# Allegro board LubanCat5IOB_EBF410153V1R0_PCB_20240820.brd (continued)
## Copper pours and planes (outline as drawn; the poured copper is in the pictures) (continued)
VCC_3V3_S3 on ART03: 36.17,18.35 32.74,18.35 32.11,17.72 32.11,14.39 31.62,13.91 25.83,13.91 25.35,14.39 25.35,18.81 24.84,19.32 4.11,19.32 3.71,18.91 3.71,17.24 4.04,16.91 22.73,16.91 23.09,16.55 23.09,12.84 23.75,12.18 33.68,12.18 34.06,12.56 34.06,16.65 34.57,17.16 36.14,17.16 36.4,17.41 36.4,18.13
VCC_3V3_S3 on ART04: 9.63,65.85 9.17,66.31 9.17,86.96 8.97,87.16 6.91,87.16 6.71,86.96 6.71,63.51 7.49,62.73 22.78,62.73 23.37,62.14 23.37,58.18 23.83,57.72 28.09,57.72 28.75,57.06 28.75,54.24 29.08,53.91 31.11,53.91 31.45,53.58 31.45,36.31 31.95,35.8 34.32,35.8 34.85,35.27 34.85,17.82 34.98,17.69 36.35,17.69 36.5,17.85 36.5,36.72 36.09,37.12 33.32,37.12 32.69,37.76 32.69,55.72 31.45,56.96 31.45,59.93 30.73,60.64 26.72,60.64 26.01,61.36 26.01,65.45 25.6,65.85
VCC_3V3_S3 on ART04: 95.94,38.6 96.01,38.42 96.19,38.34 97.36,38.34 97.54,38.42 97.61,38.6 97.61,38.78 97.54,38.95 97.36,39.03 96.19,39.03 96.01,38.95 95.94,38.78
VCC_3V3_S3 on PWR05: 34.77,17.36 34.85,17.18 35.03,17.11 39.75,17.11 39.93,17.18 40.01,17.36 40.01,18.07 39.93,18.25 39.75,18.33 35.03,18.33 34.85,18.25 34.77,18.07
VCC_5V0_S0 on TOP: 161.85,50.82 161.85,48.43 162.05,48.22 163.37,48.22 163.37,50.82 163.18,51.02 162.04,51.02
VCC_5V0_S0 on TOP: 40.51,71.41 40.59,71.23 40.77,71.16 41.78,71.16 41.96,71.23 42.04,71.41 42.04,72.58 41.96,72.76 41.78,72.84 40.77,72.84 40.59,72.76 40.51,72.58
VCC_5V0_S0 on TOP: 28.7,70.3 28.78,70.12 28.96,70.04 30.05,70.04 30.23,70.12 30.3,70.3 30.3,71.49 30.23,71.67 30.05,71.74 28.96,71.74 28.78,71.67 28.7,71.49
VCC_5V0_S0 on TOP: 162.03,83.25 162.1,83.07 162.28,83 163.12,83 163.3,83.07 163.37,83.25 163.37,84.24 163.3,84.42 163.12,84.5 162.28,84.5 162.1,84.42 162.03,84.24
VCC_5V0_S0 on TOP: 161.85,68.3 161.85,65.81 162.05,65.61 163.37,65.61 163.37,66.9 163.47,67 163.75,67 163.86,67.11 163.86,68.3 163.73,68.43 161.98,68.43
VCC_5V0_S0 on TOP: 127.64,34.43 127.64,32.6 127.43,32.4 125.88,32.4 125.68,32.6 125.68,33.85 126.8,33.85 127.03,34.08 127.03,34.43
VCC_5V0_S0 on TOP: 12.57,65.98 22.05,65.98 22.68,65.34 24.66,65.34 24.97,65.04 24.97,64.38 26.16,64.38 26.16,66.31 25.86,66.61 23.16,66.61 21.89,67.88 20.5,67.88 20.12,68.26 16.28,68.26 16.03,68.01 16.03,67.63 15.77,67.38 12.57,67.38
VCC_5V0_S0 on BOTTOM: 163.19,32.1 149.1,32.1 148.95,32.25 148.95,34.41 149.12,34.58 162.1,34.58 162.31,34.38 162.31,33.54 162.48,33.37 163.37,33.37 163.37,32.27
VCC_5V0_S0 on BOTTOM: 161.85,48.86 161.92,48.68 162.1,48.61 163.19,48.61 163.37,48.68 163.45,48.86 163.45,50.79 163.37,50.97 163.19,51.04 162.1,51.04 161.92,50.97 161.85,50.79
VCC_5V0_S0 on BOTTOM: 161.95,68.43 163.27,68.43 163.37,68.32 163.37,67.56 163.53,67.41 163.73,67.41 163.86,67.28 163.86,67.08 163.78,67 161.93,67 161.82,67.11 161.82,68.3
VCC_5V0_S0 on BOTTOM: 125.58,32.58 125.65,32.4 125.83,32.32 127.2,32.32 127.38,32.4 127.46,32.58 127.46,33.62 127.38,33.8 127.2,33.87 125.83,33.87 125.65,33.8 125.58,33.62
VCC_5V0_S0 on BOTTOM: 11.68,84.39 11.76,84.21 11.94,84.14 12.85,84.14 13.03,84.21 13.11,84.39 13.11,86.17 13.03,86.35 12.85,86.43 11.94,86.43 11.76,86.35 11.68,86.17
VCC_5V0_S0 on ART03: 20.7,65.8 24.87,65.8 25.35,66.28 25.35,69.66 25.88,70.2 32.84,70.2 33.1,70.45 33.1,71.26 33.35,71.52 41.83,71.52 42.11,71.8 42.11,72.76 41.91,72.96 22.96,72.96 22.66,72.66 22.66,69.56 22.4,69.31 20.65,69.31 20.45,69.1 20.45,66.05
VCC_5V0_S0 on ART04: 120.45,28.69 120.19,28.95 120.19,30.29 120.5,30.6 125.2,30.6 125.5,30.9 125.5,32.63 125.68,32.81 127.58,32.81 127.79,32.6 127.79,30.88 128.07,30.6 131.72,30.6 133.96,32.83 147.9,32.83 148.16,33.09 148.16,34.41 148.31,34.56 149.3,34.56 149.5,34.36 149.5,30.85 148.95,30.29 135.05,30.29 133.45,28.69
VCC_5V0_S0 on ART04: 161.85,17.17 161.85,59.56 162.15,59.87 162.97,59.87 163.27,60.17 163.27,66.8 163.07,67 162.05,67 161.85,67.21 161.85,96.43 161.06,97.22 99.9,97.22 99.42,97.7 99.42,98.22 95,98.22 95,97.31 94.69,97 88.98,97 88.67,97.31 88.67,98.98 44.86,98.98 43.71,97.84 39.32,97.84 38.94,97.46 38.94,94.07 38.29,93.42 14.63,93.42 14.02,92.81 14.02,85.05 14.35,84.72 15.34,84.72 15.82,84.24 15.82,70.2 16.26,69.76 20.14,69.76 20.52,69.38 20.52,68.06 20.78,67.81 21.72,67.81 22.02,67.5 22.02,66.21 21.79,65.98 9.98,65.98 9.5,66.46 9.5,96.03 9.88,96.41 16.03,96.41 16.72,97.1 27.64,97.1 28.02,97.48 28.02,101.46 28.53,101.98 165.89,101.98 166.55,101.32 166.55,17.08 166,16.53 162.48,16.53
VCC_12V on TOP: 11.96,51.74 11.96,54.05 12.24,54.33 16.64,54.33 16.92,54.05 16.92,52.32 15.49,52.32 14.91,51.74
VCC_12V on TOP: 44.91,71.36 44.98,71.18 45.16,71.11 46.18,71.11 46.36,71.18 46.43,71.36 46.43,72.56 46.36,72.74 46.18,72.81 45.16,72.81 44.98,72.74 44.91,72.56
VCC_12V on TOP: 155.96,48.71 156.03,48.53 156.21,48.45 157.56,48.45 157.74,48.53 157.81,48.71 157.81,53.05 157.74,53.23 157.56,53.3 156.21,53.3 156.03,53.23 155.96,53.05
VCC_12V on TOP: 17.58,29.08 15.14,29.08 14.99,28.93 11.33,28.93 11.15,29.11 11.15,31.39 11.35,31.6 15.01,31.6 15.01,30.38 15.21,30.17 16.03,30.17 16.23,29.97 16.23,29.51 16.38,29.36 17.58,29.36 17.63,29.31 17.63,29.13
VCC_12V on TOP: 9.98,18.36 10.06,18.18 10.24,18.11 13.41,18.11 13.59,18.18 13.67,18.36 13.67,20.27 13.59,20.45 13.41,20.52 10.24,20.52 10.06,20.45 9.98,20.27
VCC_12V on TOP: 13.28,74.72 13.28,77.64 13.11,77.82 12.78,77.82 12.6,77.99 12.6,79.62 12.42,79.8 11.94,79.8 11.71,80.02 11.71,81.85 11.56,82.01 11.28,82.01 11.1,82.18 11.1,82.67 10.97,82.79 10.03,82.79 10.03,84.6 13.61,84.6 13.87,84.85 16.15,84.85 16.15,82.31 15.98,82.13 15.57,82.13 15.44,82.01 15.44,74.72 15.27,74.54 13.46,74.54
VCC_12V on TOP: 33.5,69.84 33.58,69.66 33.76,69.59 34.75,69.59 34.93,69.66 35,69.84 35,70.91 34.93,71.09 34.75,71.16 33.76,71.16 33.58,71.09 33.5,70.91
VCC_12V on TOP: 152.12,68.58 152.12,66.69 151.94,66.51 149.76,66.51 149.61,66.66 149.61,67.78 149.76,67.93 150.72,67.93 150.88,68.09 150.88,68.76 151.94,68.76
VCC_12V on TOP: 12.37,48.49 12.37,46.02 16.71,46.02 16.92,46.23 16.92,47.14 15.09,47.14 14.81,47.42 14.81,48.46 14.63,48.64 12.52,48.64
VCC_12V on TOP: 11.96,57.73 11.96,59.36 12.22,59.61 16.69,59.61 16.94,59.36 16.94,58.01 15.19,58.01 14.91,57.73
VCC_12V on TOP: 12.24,37.69 16.71,37.69 16.92,37.49 16.92,36.22 16.71,36.02 12.29,36.02 12.09,36.22 12.09,37.54
VCC_12V on TOP: 151,53.28 152.4,53.28 152.58,53.1 152.58,49.72 152.37,49.52 150.06,49.52 149.91,49.67 149.91,51.75 150.06,51.91 150.85,51.91 151,52.06
VCC_12V on TOP: 19.56,38.61 19.63,38.43 19.81,38.35 22.35,38.35 22.53,38.43 22.61,38.61 22.61,40.13 22.53,40.31 22.35,40.38 19.81,40.38 19.63,40.31 19.56,40.13
VCC_12V on BOTTOM: 149.91,49.72 149.99,49.54 150.16,49.47 151.99,49.47 152.17,49.54 152.25,49.72 152.25,51.65 152.17,51.83 151.99,51.91 150.16,51.91 149.99,51.83 149.91,51.65
VCC_12V on BOTTOM: 155.93,48.73 156,48.55 156.18,48.48 157.35,48.48 157.53,48.55 157.61,48.73 157.61,51.65 157.53,51.83 157.35,51.91 156.18,51.91 156,51.83 155.93,51.65
VCC_12V on ART03: 33.38,69.66 33.38,71.11 33.58,71.31 41.99,71.31 42.39,71.72 42.39,72.94 42.09,73.24 29.95,73.24 29.64,73.55 29.64,75.55 29.24,75.96 23.34,75.96 23.09,76.21 23.09,79.19 23.27,79.36 30.81,79.36 33.88,76.29 34.98,76.29 35.61,75.66 45.59,75.66 46.41,74.84 46.41,69.74 46.13,69.46 33.58,69.46
VCC_12V on ART04: 41.86,9.78 41.86,11.32 43.59,11.32 43.94,11.67 43.94,12.39 44.3,12.75 99.8,12.75 100.84,13.79 100.84,19.93 101.35,20.44 104.06,20.44 104.6,19.9 104.6,14.87 105.23,14.24 153.06,14.24 157.58,18.76 157.58,47.67 157.28,47.98 155.22,47.98 154.91,48.28 154.91,48.89 154.58,49.22 149.66,49.22 149.3,49.58 149.3,61.57 149.66,61.92 160.63,61.92 160.88,62.18 160.88,64.79 160.71,64.97 151.33,64.97 151.08,65.23 151.08,65.78 150.9,65.96 150.14,65.96 150.11,65.94 149.76,65.94 149.53,66.17 149.53,67.79 149.78,68.05 161.95,68.05 163.27,66.72 163.27,60.35 162.84,59.92 162.23,59.92 161.62,59.31 161.62,15.46 160.73,14.57 158.6,14.57 157.07,13.05 157.07,10.86 155.99,9.78
VCC_12V on PWR05: 9.78,80.25 9.78,12.28 10.44,11.62 41,11.62 41.35,11.27 41.35,10.03 41.58,9.8 43.26,9.8 43.48,10.03 43.48,15.52 42.98,16.03 20.83,16.03 19.81,17.04 19.81,36.83 20.6,37.62 22.45,37.62 22.96,38.12 22.96,41.58 22.53,42.01 20.22,42.01 19.81,42.42 19.81,76.06 20.24,76.49 23.29,76.49 23.7,76.9 23.7,80.43 23.44,80.69 10.21,80.69
VCCA1V8_CODEC on BOTTOM: 17.35,69.81 17.35,70.63 16.69,71.29 16.69,76.55 16.79,76.65 18.72,76.65 18.72,73.7 18.34,73.32 18.34,69.92 18.24,69.81
VCCA3V3_CODEC on BOTTOM: 22.12,69.86 22.12,70.7 21.92,70.91 21.92,74.36 23.55,74.36 23.55,73.75 22.63,73.75 22.53,73.65 22.53,71.19 22.91,70.8 22.91,69.86
VCCA_1V8_S0 on TOP: 38.58,16.07 39.75,16.07 39.95,15.86 44.86,15.86 45.54,16.55 45.54,18.02 45.77,18.02 45.77,15.69 45.24,15.15 40.18,15.15 40.01,15.33 38.58,15.33 38.48,15.43 38.48,15.97
VCCA_1V8_S0 on BOTTOM: 18.95,70.65 18.95,68.39 19.18,68.16 21.84,68.16 22.02,68.34 22.02,68.77 21.82,68.98 19.91,68.98 19.76,69.13 19.76,70.65
VCCA_1V8_S0 on ART04: 20.95,68.7 23.16,68.7 23.39,68.47 23.39,67.68 23.75,67.32 27.41,67.32 27.81,66.92 27.81,63.41 28.42,62.8 30.78,62.8 33.15,60.44 33.15,57.67 34.62,56.2 34.62,38.95 34.87,38.7 37.87,38.7 38.23,38.34 38.23,16.58 38.46,16.35 39.9,16.35 40.13,16.12 40.13,15.2 39.9,14.98 36.83,14.98 36.65,15.15 36.65,36.77 36.14,37.28 33.45,37.28 32.87,37.86 32.87,55.87 31.62,57.11 31.62,60.04 30.78,60.87 26.92,60.87 26.21,61.58 26.21,65.62 25.86,65.98 22.43,65.98 22.23,66.18 22.23,67.63 21.82,68.04 20.95,68.04 20.8,68.19 20.8,68.54
VCCA_3V3_S0 on TOP: 45.09,18.02 45.09,17.16 44.58,16.65 40.36,16.65 39.75,17.26 38.61,17.26 38.48,17.13 38.48,16.73 38.66,16.55 39.6,16.55 40.11,16.04 44.7,16.04 45.42,16.75 45.42,18.02
VCCA_3V3_S0 on BOTTOM: 20.52,70.65 20.52,69.33 20.7,69.15 21.89,69.15 22.02,69.28 22.02,69.56 21.87,69.71 21.44,69.71 21.31,69.84 21.31,70.65
VCCA_3V3_S0 on ART04: 20.95,69.76 26.97,69.76 27.14,69.6 27.14,69.12 27.33,68.93 29.92,68.93 30.18,68.67 30.18,65.65 31.32,64.51 35.31,64.51 36.02,63.79 36.02,40.81 36.3,40.53 39.9,40.53 40.49,39.94 40.49,16.88 40.26,16.65 38.63,16.65 38.4,16.88 38.4,38.5 38.05,38.85 35.05,38.85 34.8,39.11 34.8,56.53 33.5,57.83 33.5,60.59 30.99,63.11 28.65,63.11 28.02,63.74 28.02,67.12 27.58,67.55 23.88,67.55 23.62,67.81 23.62,68.67 23.37,68.93 20.95,68.93 20.8,69.08 20.8,69.61
VDD_CAM0_5V on TOP: 166.6,80.2 165.28,80.2 165.28,80.89 165.18,80.99 163.78,80.99 163.78,81.85 163.63,82.01 162.76,82.01 162.76,82.62 166.42,82.62 166.6,82.44
VDD_CAM1_5V on BOTTOM: 166.62,71.01 165.28,71.01 165.28,70.58 165,70.3 163.78,70.3 163.78,69.41 163.65,69.28 162.76,69.28 162.76,68.65 166.42,68.65 166.62,68.85
VDD_CAM2_5V on TOP: 166.6,62.8 165.3,62.8 165.3,63.34 165.05,63.59 163.78,63.59 163.78,64.4 163.55,64.63 162.76,64.63 162.76,65.24 166.37,65.24 166.6,65.01
VDD_CAM3_5V on BOTTOM: 166.6,53.61 163.93,53.61 163.78,53.46 163.78,52.03 163.6,51.86 162.79,51.86 162.79,51.27 166.37,51.27 166.6,51.5
VDD_CAM4_5V on TOP: 166.6,45.4 165.3,45.4 165.3,46.07 165.18,46.19 163.78,46.19 163.78,47.08 163.63,47.23 162.76,47.23 162.76,47.82 166.32,47.82 166.6,47.54
VDD_CAM5_5V on BOTTOM: 166.6,36.21 165.3,36.21 165.3,35.6 165.07,35.37 163.78,35.37 163.78,34.51 163.6,34.33 162.76,34.33 162.76,33.75 166.37,33.75 166.6,33.97
VDD_LCD0_3V3 on TOP: 7.87,90.13 8.74,90.13 8.94,89.93 8.94,87.39 9.55,86.78 9.55,81.22 9.27,80.94 7.9,80.94 7.9,85.71 7.67,85.94 7.67,89.93
VDD_LCD0_3V3 on BOTTOM: 7.72,90.01 7.72,86.91 7.9,86.73 9.19,86.73 9.19,90.06 9.04,90.21 7.92,90.21
VDD_LCD0_5V on TOP: 7.67,81.93 7.67,85.49 7.42,85.74 7.42,90.01 7.29,90.13 5.77,90.13 5.61,89.98 5.61,82.31 5.99,81.93
VDD_LCD0_5V on BOTTOM: 11.42,90.2 11.18,90.44 7.85,90.44 7.54,90.13 7.54,87.92 7.34,87.72 6.58,87.72 6.38,87.92 6.38,90.9 7.06,91.58 12.04,91.58 12.34,91.28 12.34,86.73 11.58,86.73 11.42,86.9
VDD_LCD1_3V3 on TOP: 15.04,64.38 15.04,65.32 14.63,65.72 9.73,65.72 9.53,65.52 9.53,64.43 9.73,64.23 11.66,64.23 11.81,64.38
VDD_LCD1_3V3 on BOTTOM: 9.45,64.45 9.52,64.28 9.7,64.2 10.87,64.2 11.05,64.28 11.13,64.45 11.13,65.5 11.05,65.68 10.87,65.75 9.7,65.75 9.52,65.68 9.45,65.5
VDD_LCD1_3V3 on BOTTOM: 7.67,70.74 5.77,70.74 5.64,70.61 5.64,70.08 5.79,69.93 7.67,69.93
VDD_LCD1_5V on TOP: 23.67,64.38 20.27,64.38 20.04,64.15 18.72,64.15 18.57,64.3 18.57,65.55 18.72,65.7 21.84,65.7 22.58,64.96 23.67,64.96
VDD_LCD1_5V on BOTTOM: 6.3,69.69 6.3,66.92 6.88,66.33 11.1,66.33 11.46,65.98 11.46,62.75 11.81,62.4 19.84,62.4 20.02,62.58 20.02,66.66 19.58,67.1 13.79,67.1 13.39,67.5 8.05,67.5 7.67,67.88 7.67,69.69
(no net) on TOP: 72.21,75.53 72.36,75.53 72.47,75.43 72.47,75.12 72.57,75.02 72.9,75.02 73,74.92 73,74.18 73.74,73.45 73.74,71.39 72.62,71.39 72.62,73.19 72.14,73.67 72.14,75.45
(no net) on TOP: 55.03,74.3 55.34,73.99 55.34,71.39 54.22,71.39 54.22,73.41 54.06,73.57 54.06,74.76 53.74,75.08 53.74,75.72 53.85,75.83 54.66,75.83 54.8,75.69 54.8,75.34 55.03,75.11
CAN1_H on TOP (solid shape): 95.8,13.05 94.87,12.29 94.18,12.99 94.15,13.05 94.18,13.11 94.87,13.81
CAN2_H on TOP (solid shape): 104.67,13.05 103.75,12.3 103.07,12.99 103.04,13.05 103.07,13.11 103.75,13.8
HDMI0_5V on BOTTOM: 86.23,98.17 86.31,97.99 86.49,97.92 88.52,97.92 88.7,97.99 88.77,98.17 88.77,101.34 88.7,101.52 88.52,101.6 86.49,101.6 86.31,101.52 86.23,101.34
HDMI0_5V on ART04: 84.48,84.43 84.55,84.25 84.73,84.17 88.21,84.17 88.39,84.25 88.47,84.43 88.47,99.36 88.39,99.54 88.21,99.62 84.73,99.62 84.55,99.54 84.48,99.36
HDMI1_5V on BOTTOM: 95.12,98.17 95.2,97.99 95.38,97.92 97.28,97.92 97.46,97.99 97.54,98.17 97.54,101.34 97.46,101.52 97.28,101.6 95.38,101.6 95.2,101.52 95.12,101.34
HDMI1_5V on ART04: 95.2,84.38 95.27,84.2 95.45,84.12 98.96,84.12 99.14,84.2 99.21,84.38 99.21,99.31 99.14,99.49 98.96,99.57 95.45,99.57 95.27,99.49 95.2,99.31
M2EKEY_3V3 on TOP: 159.08,59.1 159.08,62.91 158.75,63.24 158.39,63.24 158.39,64.51 158.55,64.66 160.66,64.66 160.78,64.53 160.78,63.39 160.48,63.08 160.48,59.1
M2EKEY_3V3 on BOTTOM: 158.17,63.49 158.24,63.31 158.42,63.24 160.53,63.24 160.71,63.31 160.78,63.49 160.78,64.43 160.71,64.61 160.53,64.68 158.42,64.68 158.24,64.61 158.17,64.43
M2EKEY_3V3 on BOTTOM: 141.17,63.47 141.25,63.29 141.43,63.22 141.76,63.22 141.94,63.29 142.01,63.47 142.01,66.37 141.94,66.55 141.76,66.62 141.43,66.62 141.25,66.55 141.17,66.37
M2EKEY_3V3 on BOTTOM: 124.49,64.77 124.49,63.12 124.92,62.69 124.92,62.31 124.79,62.18 123.62,62.18 123.49,62.31 123.49,63.02 123.7,63.22 123.7,64.77
M2EKEY_3V3 on ART04: 125.32,62.5 125.32,74.93 125.6,75.21 132.16,75.21 132.54,74.83 132.54,62.76 133.22,62.08 160.32,62.08 160.76,62.51 160.76,64.57 160.53,64.79 142.19,64.79 141.76,65.23 141.76,66.39 141.3,66.85 137.02,66.85 136.42,67.45 136.42,76.77 135.88,77.32 123.02,77.32 122.4,76.7 122.4,62.47 122.75,62.13 124.95,62.13
M2PCIE_3V3 on TOP: 153.7,78.25 152.63,78.25 152.32,78.55 152.32,85.1 152.68,85.46 152.68,87.24 151.03,87.24 150.83,87.04 150.83,77.26 151.28,76.8 153.7,76.8
M2PCIE_3V3 on TOP: 158.17,80.23 156.79,80.23 156.62,80.41 156.62,82.74 156.34,83.02 154.69,83.02 154.43,83.28 154.43,87.24 156.18,87.24 156.18,84.68 156.44,84.43 157.18,84.43 157.4,84.2 157.4,81.83 157.61,81.63 158.19,81.63 158.34,81.47 158.34,80.41
M2PCIE_3V3 on BOTTOM: 168.22,85.29 168.3,85.11 168.48,85.04 170.05,85.04 170.23,85.11 170.31,85.29 170.31,88.21 170.23,88.39 170.05,88.47 168.48,88.47 168.3,88.39 168.22,88.21
M2PCIE_3V3 on ART03: 150.93,80.29 166.85,80.29 167.79,81.23 169.9,81.23 170.18,81.51 170.18,87.4 169.72,87.86 167.59,87.86 167.08,87.35 167.08,83.44 166.78,83.13 152.02,83.13 151.54,83.62 150.95,83.62 150.8,83.46 150.8,80.42
MINIPCIE_3V3 on TOP: 130.28,60.21 130.35,60.03 130.53,59.96 132.26,59.96 132.44,60.03 132.51,60.21 132.51,60.52 132.44,60.7 132.26,60.77 130.53,60.77 130.35,60.7 130.28,60.52
MINIPCIE_3V3 on TOP: 124.99,71.4 125.07,71.22 125.25,71.14 126.16,71.14 126.34,71.22 126.42,71.4 126.42,74.52 126.34,74.7 126.16,74.78 125.25,74.78 125.07,74.7 124.99,74.52
MINIPCIE_3V3 on TOP: 120.45,60.21 120.52,60.03 120.7,59.96 123.8,59.96 123.98,60.03 124.05,60.21 124.05,60.54 123.98,60.72 123.8,60.8 120.7,60.8 120.52,60.72 120.45,60.54
MINIPCIE_3V3 on TOP: 143.81,60.01 144.96,60.01 145.19,60.24 145.19,61.36 144.96,61.58 144.02,61.58 143.81,61.38
MINIPCIE_3V3 on TOP: 153.82,61.43 153.82,62.85 152.27,62.85 152.15,62.98 152.15,66.24 149.83,66.24 149.63,66.04 149.63,63.41 149.81,63.24 150.09,63.24 150.39,62.93 150.39,61.74 150.7,61.43
MINIPCIE_3V3 on BOTTOM: 125.53,73.66 125.6,73.48 125.78,73.4 126.39,73.4 126.57,73.48 126.64,73.66 126.64,74.52 126.57,74.7 126.39,74.78 125.78,74.78 125.6,74.7 125.53,74.52
MINIPCIE_3V3 on BOTTOM: 149.96,65.93 152.07,65.93 152.32,65.67 152.32,62.96 151.74,62.96 151.74,63.34 151.56,63.51 150.01,63.51 149.83,63.69 149.83,65.8
MINIPCIE_3V3 on ART03: 151.08,65.75 150.9,65.93 149.02,65.93 148.82,65.72 148.82,62.45 148.46,62.09 122.78,62.09 122.53,61.84 122.53,60.26 122.76,60.04 150.65,60.04 151.08,60.47
MINIPCIE_3V3 on ART04: 122.78,61.84 125.2,61.84 125.6,62.24 125.6,74.59 125.81,74.79 128.57,74.79 128.96,74.41 128.96,59.78 128.65,59.48 122.73,59.48 122.4,59.81 122.4,61.46
RS232_R2IN on BOTTOM (solid shape): 145.21,14.64 145.26,14.66 145.31,14.64 146,13.95 145.26,13.03 144.51,13.95
RS485_1_B on TOP (solid shape): 121.17,13.05 120.24,12.32 119.58,12.99 119.55,13.05 119.58,13.11 120.24,13.78
SATA_5V0 on TOP: 22.61,33.2 28.63,33.2 28.85,33.43 28.85,34.95 28.65,35.15 26.09,35.15 25.91,34.97 25.91,34.75 25.73,34.57 22.61,34.57
SATA_5V0 on BOTTOM: 26.42,33.78 26.49,33.6 26.67,33.53 28.7,33.53 28.88,33.6 28.96,33.78 28.96,35.18 28.88,35.36 28.7,35.43 26.67,35.43 26.49,35.36 26.42,35.18
SATA_5V0 on ART03: 25.91,34.94 25.91,14.75 26.42,14.24 31.57,14.24 31.83,14.49 31.83,17.16 31.57,17.41 29.34,17.41 28.83,17.92 28.83,34.94 28.57,35.19 26.16,35.19
SATA_12V on TOP: 17.35,23.85 17.35,19.96 17.45,19.86 17.45,18.07 16.84,17.46 16.84,13.1 16.15,12.41 16.15,11.11 16.94,10.33 16.94,8.57 16.67,8.3 11.78,8.3 11.48,8.6 11.48,10.64 12.09,11.25 12.09,13.44 12.52,13.87 14.05,13.87 14.43,14.25 14.43,20.09 14.27,20.24 13.13,20.24 13.13,21.18 14.38,21.18 14.63,21.44 14.63,23.65 14.83,23.85
SATA_12V on BOTTOM: 11.18,8.36 11.25,8.18 11.43,8.1 29.84,8.1 30.02,8.18 30.1,8.36 30.1,11.25 30.02,11.43 29.84,11.51 11.43,11.51 11.25,11.43 11.18,11.25
N16593687 on TOP: 19.76,32.46 19.76,30.68 20.37,30.68 20.37,32.46
N16593695 on TOP: 17.5,28.88 20.13,28.88 20.75,29.5 20.75,32.46 23.27,32.46 23.62,32.1 23.62,31.23 23.9,30.95 25.45,30.95 25.45,29.05 22.43,29.05 21.35,27.96 18.14,27.96 17.96,28.14 17.96,28.45 17.83,28.57 17.5,28.57 17.42,28.65 17.42,28.8
N16594691 on TOP: 18.06,29.11 19.8,29.11 20.37,29.68 20.37,30.3 19.76,30.3 19.76,29.94 19.36,29.54 18.06,29.54 17.98,29.46 17.98,29.18
N16606404 on TOP (solid shape): 72.47,75.43 72.47,75.12 72.57,75.02 72.9,75.02 73,74.92 73,74.18 73.74,73.45 73.74,71.39 72.62,71.39 72.62,73.19 72.14,73.67 72.14,75.45 72.21,75.53 72.36,75.53
N16612146 on TOP (solid shape): 54.21,75.81 54.27,75.8 54.69,75.8 54.8,75.69 54.8,75.34 55.03,75.11 55.03,74.3 55.34,73.99 55.34,71.39 54.22,71.39 54.22,73.41 54.06,73.57 54.06,74.76 53.74,75.08 53.74,75.72 53.85,75.83 54.15,75.83
N16630071 on BOTTOM: 22.94,72.76 24.56,72.76 24.56,74.36 23.95,74.36 23.95,73.5 23.8,73.34 22.94,73.34
N16783872 on TOP: 124.46,76.81 124.53,76.63 124.71,76.55 126.59,76.55 126.77,76.63 126.85,76.81 126.85,78.1 126.77,78.28 126.59,78.36 124.71,78.36 124.53,78.28 124.46,78.1
N16803397 on TOP: 153.24,72.2 153.24,70.02 153.29,69.97 154.18,69.97 154.18,72.07 154.05,72.2
N16803401 on TOP: 150.9,69 152.76,69 153.06,69.31 153.06,72.96 153.29,73.19 153.67,73.19 153.67,74.61 151.38,74.61 151.38,73.22 152.04,73.22 152.22,73.04 152.22,69.84 152.1,69.71 150.9,69.71
N16835425 on TOP: 17.17,47.12 17.17,45.26 17.4,45.03 21.08,45.03 21.34,45.29 21.34,46.33 21.46,46.46 24.77,46.46 24.77,47.83 19.96,47.83 19.71,47.57 19.71,46.23 19.51,46.02 17.98,46.02 17.88,46.13 17.88,47.12
N16835491 on TOP: 18.08,44.04 18.16,43.86 18.34,43.79 20.27,43.79 20.45,43.86 20.52,44.04 20.52,44.5 20.45,44.68 20.27,44.75 18.34,44.75 18.16,44.68 18.08,44.5
N16843509 on TOP: 151,53.53 152.98,53.53 153.16,53.71 153.16,57.53 153.29,57.66 153.8,57.66 153.8,59.05 151.51,59.05 151.51,57.66 151.89,57.66 152.12,57.43 152.12,54.35 151.99,54.22 151,54.22
N16843993 on TOP: 153.37,56.71 153.37,55.23 153.42,55.18 153.42,54.47 154.31,54.47 154.31,56.53 154.13,56.71
N16890968 on TOP: 11.43,73.34 11.43,71.52 11.61,71.34 12.24,71.34 12.24,72.53 12.34,72.63 12.34,73.34
N16890980 on TOP: 14.73,74.28 12.9,74.28 12.65,74.03 12.65,69.76 12.83,69.59 14.86,69.59 14.86,70.98 13.72,70.98 13.59,71.11 13.59,73.5 13.67,73.57 14.73,73.57
N16891638 on TOP: 18.08,55.85 18.16,55.67 18.34,55.6 20.22,55.6 20.4,55.67 20.47,55.85 20.47,56.34 20.4,56.52 20.22,56.59 18.34,56.59 18.16,56.52 18.08,56.34
N16891644 on TOP: 17.17,58.95 17.17,57.07 17.4,56.84 21.26,56.84 21.51,57.1 21.51,58.24 21.79,58.52 24.79,58.52 24.79,59.92 20.09,59.92 19.76,59.59 19.76,57.89 19.61,57.73 18.06,57.73 17.88,57.91 17.88,58.95
N16892291 on TOP: 17.17,53.21 17.17,51.41 17.45,51.13 20.8,51.13 21.01,50.93 21.01,50.29 22.4,50.29 22.4,52.58 20.62,52.58 20.12,52.07 18.06,52.07 17.88,52.25 17.88,53.19 17.86,53.21
N16892339 on TOP: 18.08,50.14 18.16,49.96 18.34,49.88 20.19,49.88 20.37,49.96 20.45,50.14 20.45,50.6 20.37,50.78 20.19,50.85 18.34,50.85 18.16,50.78 18.08,50.6
N16935613 on TOP: 156.34,53.51 158.27,53.51 158.5,53.74 158.5,57.9 158.29,58.1 157.15,58.1 156.87,58.38 156.87,61.38 155.5,61.38 155.5,56.53 155.93,56.1 157.28,56.1 157.53,55.84 157.53,54.45 157.3,54.22 156.34,54.22
N16935675 on TOP: 158.7,56.71 158.7,54.47 159.64,54.47 159.64,56.56 159.49,56.71
N17085599 on TOP: 17.17,37.46 17.17,35.61 17.4,35.38 21.21,35.38 21.46,35.64 21.46,36.63 21.64,36.8 24.89,36.8 24.89,38.2 19.89,38.2 19.66,37.97 19.66,36.55 19.46,36.35 18.03,36.35 17.88,36.5 17.88,37.46
N17085653 on TOP: 18.08,34.42 18.16,34.24 18.34,34.16 20.22,34.16 20.4,34.24 20.47,34.42 20.47,34.85 20.4,35.03 20.22,35.1 18.34,35.1 18.16,35.03 18.08,34.85
N17139392 on TOP: 106.17,41.04 106.17,38.19 105.82,37.84 101.9,37.84 101.9,39.05 104.5,39.05 104.93,39.49 104.93,41.04 105.21,41.32 105.89,41.32
N17139392 on BOTTOM: 100.48,41.42 106.05,41.42 106.32,41.14 106.32,39.16 105.92,38.75 101.35,38.75 100.97,39.13 100.97,39.69 100.46,40.2 100.46,41.39
N17139440 on BOTTOM: 99.77,30.77 99.77,31.79 99.44,32.12 99.44,37.23 98.32,37.23 98.09,37 98.09,31 98.32,30.77
N17139454 on BOTTOM: 99.44,41.34 99.44,39.66 99.67,39.44 100.41,39.44 100.41,38.17 98.65,38.17 98.42,38.39 98.42,41.37 99.42,41.37
N17141731 on TOP: 26.42,79.49 26.49,79.31 26.67,79.24 27,79.24 27.18,79.31 27.25,79.49 27.25,82.41 27.18,82.59 27,82.67 26.67,82.67 26.49,82.59 26.42,82.41
N17141731 on TOP: 30.89,70.25 30.89,71.67 30.58,71.97 29.92,71.97 29.79,72.1 29.79,82.41 29.95,82.56 31.7,82.56 31.72,82.54 31.72,72.76 32.28,72.2 32.89,72.2 33.12,71.97 33.12,70.22 30.91,70.22
N17141731 on ART04: 26.31,80.33 26.39,80.15 26.57,80.08 30.18,80.08 30.35,80.15 30.43,80.33 30.43,82.41 30.35,82.59 30.18,82.67 26.57,82.67 26.39,82.59 26.31,82.41
N17141824 on TOP: 37.72,79.36 37.79,79.18 37.97,79.11 38.3,79.11 38.48,79.18 38.56,79.36 38.56,82.29 38.48,82.47 38.3,82.54 37.97,82.54 37.79,82.47 37.72,82.29
N17141824 on TOP: 41.25,73.22 41.25,82.95 41.4,83.1 43.15,83.1 43.18,83.07 43.18,72.53 43.51,72.2 44.58,72.2 44.58,71.39 42.34,71.39 42.34,73.07 42.19,73.22
N17141824 on BOTTOM: 37.64,80.18 37.72,80 37.9,79.92 41.33,79.92 41.51,80 41.58,80.18 41.58,82.46 41.51,82.64 41.33,82.72 37.9,82.72 37.72,82.64 37.64,82.46
N17143919 on TOP (solid shape): 42.83,100.05 42.85,100 42.83,99.95 42.15,99.3 40.88,100 42.15,100.7
N17143960 on TOP (solid shape): 34.02,98.1 32.75,97.5 32.2,98.05 32.18,98.1 32.2,98.15 32.75,98.7
N17143962 on TOP (solid shape): 34.02,101 32.75,100.3 32.07,100.95 32.05,101 32.07,101.05 32.75,101.7
N17144006 on TOP (solid shape): 42.64,94.96 42.66,94.9 42.64,94.84 42.15,94.35 40.87,94.9 42.15,95.45

Small or netless copper shapes (teardrops, artwork), in the pictures only: 36 on TOP, 25 on BOTTOM, 3 on ART04

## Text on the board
Ref Des/Silkscreen Bottom: NC | TX | RX | GND | J13 | M2 E KEY | J15 | MIPI DSI1 | IN7 | IN6 | IN5 | 1V8 | CAN1_L | CAN1_H | CAN2_L | 7-RX | 7-TX | CAN2_H | R2OUT | 2_RX | T2IN | 2_TX | 485_2A | R1OUT | 1_RX | 485_2B | T1IN | 1_TX | 4-RX | 4-TX | 485_1A | 485_1B | T1OUT | R1IN | T2OUT | R2IN | RS232 | SIM CARD | J21 | J37 | J33 | J35 | CAM1 | CAM3 | CAM5 | 20240820 | EBF410153V1R0
Ref Des/Silkscreen Top: J25 | PCIE3.0 X 4 | J20 | ON/OFF | RST | RECOVERY | TYPEC/DP | MASKROM | J44 | EAR | PWROUT | MIC | J11 | J41 | ADC | J3 | J1 | 5V | J38 | SATA_PWR | J39 | J4 | J2 | SATA | J40 | CAN1 | J45 | CAN2 | FAN | J29 | J28 | RTC | J22 | RS485 | J9 | USB2.0 HOST/USB3.0 OTG | J27 | J10 | RS232 | USB2.0 HOST | MINI PCIE | PWR | SYS | J19 | J24 | TX | RX | GND | J5 | MIPI DSI0 | J14 | J8 | SPK_L | 3V3 | SPK_R | 12V | ETH1 | J7 | ETH0 | J6 | J16 | OUT0 | OUT1 | J17 | UART7 | J12 | J31 | J18 | IN | J26 | J30 | UART4 | M.2 PCIE3.0 | SD CARD | IR | CAM0 | CAM2 | CAM4 | J32 | J34 | J36 | DC IN:12V | EBF410153V1R0 | 20240820
DEVICE_TYPE_BOTTOM: C15 | C112 | R43 | R44 | C224 | U5 | U6 | J7 | C17 | C85 | L4 | L13 | SS4 | SS1 | U2 | C86 | L14 | L9 | C70 | C91 | L5 | U8 | L2 | L15 | C101 | C100 | C406 | C159 | L6 | C28 | C402 | C157 | C35 | R113 | R109 | R112 | R110 | R111 | R107 | R108 | R115 | R114 | SS3 | SS2 | J6 | R53 | R52 | U7 | R35 | R93 | L11 | C69 | U9 | C72 | C73 | U4 | C19 | C18 | L3 | C45 | C37 | R8 | C59 | U1 | U10 | L8 | C10 | L1 | L10 | L7 | C118 | C119 | R21 | C163 | Y1 | R22 | C162 | J8 | J5 | C34
DEVICE_TYPE_TOP: C83 | C82 | C75 | C136 | C138 | C74 | R96 | C64 | R95 | C62 | R97 | C63 | R13 | R83 | C81 | C77 | C78 | U3 | R15 | C93 | R82 | C135 | R16 | R20 | C149 | C150 | C76 | C137 | R5 | C12 | C79 | R17 | C11 | C169 | C16 | C54 | C53 | C60 | C398 | R79 | C80 | R72 | C394 | C400 | C399 | U11 | R76 | C24 | C36 | C48 | C1 | R2 | C7 | R6 | C25 | C31 | R7 | R14 | C268 | C391 | C390 | C393 | C3 | C5 | C50 | C49 | C158 | C33 | C32 | C4 | J3 | J1 | R106 | R105 | R41 | J4 | J2 | C321 | C353 | C377 | R69 | C365 | R32 | R30 | R51 | R31 | C297 | R29 | C296 | C240 | C228 | C250 | C293 | C238 | R24 | C252 | C236 | C247 | R25 | C248 | C245 | R26 | C251 | C292 | C242 | R28 | C223 | C207 | C128 | R27 | C229 | R45 | C212 | C170 | C213 | C153 | C154 | C211 | C171 | C214 | C155 | C210 | C215 | C165 | C104 | C220 | C280 | C216 | C164 | C156 | C107 | C221 | C217 | C282 | C167 | C142 | C218 | C166 | C141 | C279 | C161 | C98 | C219 | C281 | C160 | C283 | R59 | C264 | C144 | C94 | R60 | C143 | C152 | C95 | C249 | C146 | C151 | C96 | C256 | C288 | C134 | C257 | C246 | C103 | C140 | C261 | C284 | C116 | C258 | C114 | C290 | C139 | C263 | C113 | C266 | C285 | C262 | C115 | C255 | C265 | C239 | C120 | C209 | C130 | C222 | R56 | C208 | C132 | C184 | C294 | C187 | C202 | C200 | C201 | C186 | C197 | C185 | C195 | C205 | C196 | C204 | C193 | C194 | C192 | C190 | C182 | C338 | C307 | R61 | R42 | C382 | C337 | C304 | C312 | C348 | R64 | R86 | C303 | R87 | C301 | C359 | C331 | C324 | C350 | C361 | C306 | C360 | C355 | C378 | C343 | C364 | C386 | R68 | C298 | C356 | C368 | C351 | C305 | C379 | C362 | C309 | C346 | C380 | C381 | C369 | 99 | EBF410152V0R1 | 20240605 | C260 | R80 | C87 | C61 | C84 | R81 | R94 | R19 | R18 | C14 | C13 | L12 | C71 | C47 | C92 | R12 | C65 | R36 | C46 | C88 | C89 | C66 | R9 | R4 | C52 | C267 | C42 | C44 | C148 | C90 | C43 | C397 | C58 | C259 | C51 | C20 | C392 | C22 | C291 | C57 | C244 | C6 | C23 | R84 | C387 | C395 | C237 | R11 | C111 | C38 | R3 | C21 | C401 | R75 | R74 | C30 | C125 | C9 | C396 | C388 | C39 | C41 | C67 | C8 | C126 | C124 | R1 | R10 | C68 | C389 | R73 | C403 | C127 | C2 | C26 | D1 | C404 | C405 | C102 | R118 | C269 | C27 | C29 | R104 | R100 | R103 | R101 | R102 | R98 | R99 | R57 | C328 | R71 | R91 | C314 | C326 | C327 | C300 | C374 | C206 | C299 | R77 | R65 | R66 | R78 | R88 | R67 | C108 | C145 | R54 | R55 | C227 | C225 | C123 | C231 | C235 | C234 | C230 | R33 | C232 | R50 | C241 | C129 | C226 | R116 | R23 | C243 | C121 | R34 | C56 | C122 | R117 | R46 | C175 | C174 | C40 | C173 | R49 | C172 | C110 | C97 | R47 | C99 | C147 | C278 | C287 | R48 | C109 | R58 | C168 | C253 | C131 | C117 | C133 | C105 | C106 | C198 | C183 | C295 | C254 | C199 | C233 | C191 | R37 | C189 | C188 | R40 | C289 | C177 | C178 | C286 | C203 | C180 | C181 | C179 | C176 | R39 | R38 | C372 | C334 | C347 | R62 | C316 | C335 | C325 | C354 | C375 | C383 | C384 | C310 | C341 | C336 | C358 | C376 | R63 | R85 | R92 | R70 | C333 | C349 | C352 | R89 | C311 | C302 | R90 | C313 | C322 | C385 | C317 | C318 | C332 | C370 | C340 | C315 | C371 | C367 | C344 | C308 | C320 | C330 | C319 | C323 | C366 | C357 | C339 | C363 | C373 | C329 | C345 | C55
DIMENSION: FIGURE | SIZE | 8.0 | 10.0 | 19.685 | 21.654 | 25.591 | 27.559 | 29.528 | 31.496 | 33.465 | 39.37 | 47.244 | 59.055 | 72.047 | 78.74 | 94.5 | 125.98 | 166.142 | 35.433 | 43.307 | 62.992 | 78.701 | 94.488 | 125.984 | 127.953 | 47.244x19.685 | 62.992x23.622 | 66.902x19.701 | 70.902x15.701 | 74.803x23.622 | 106.299x35.429 | DRILL CHART: TOP to BOTTOM | ALL UNITS ARE IN MILS | PLATED | NON-PLATED | QTY | 308 | 2357 | 4 | 2 | 57 | 18 | 25 | 64 | 7 | 12 | 32 | 3 | 8 | 22 | 6 | 1
